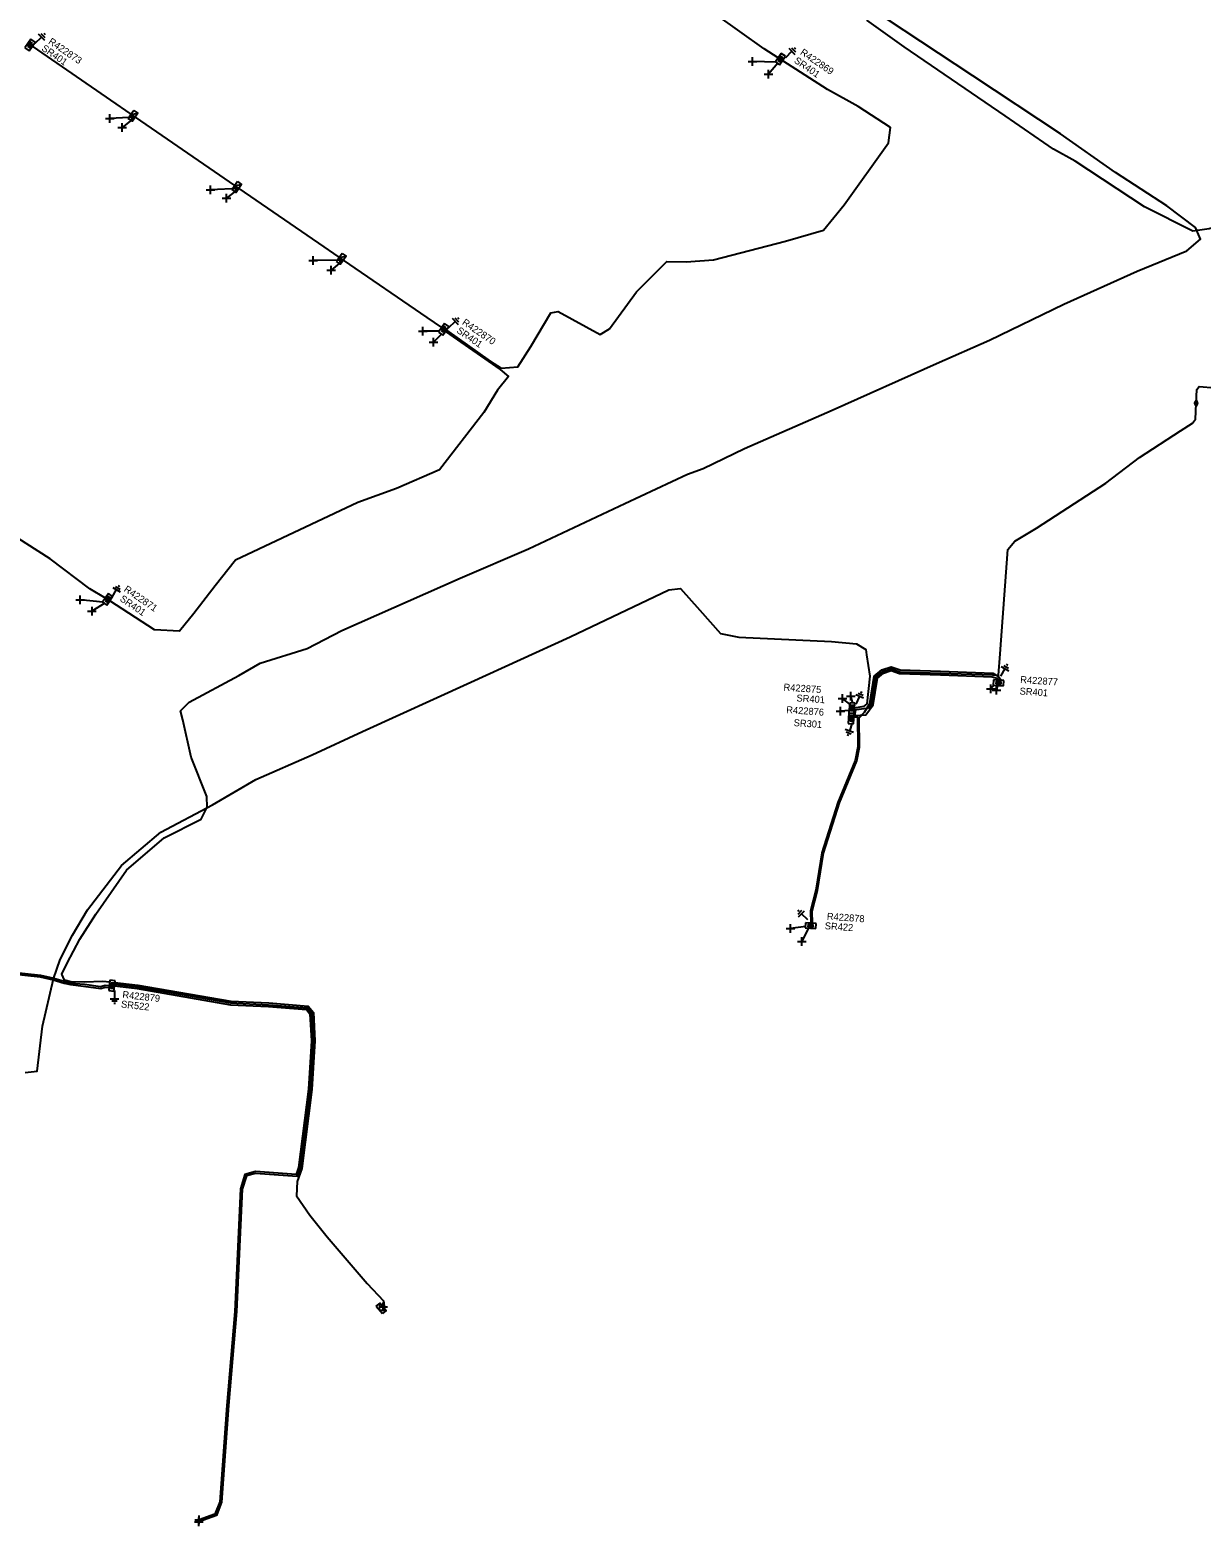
# Model space of a CAD drawing. Extents: x -540466 to -537383, y -1184038 to -1179972.
# Drawn here: x -538742.6 to -538574.2, y -1181559 to -1181344 of the extents above; entities that cross this region are included whole.
import ezdxf

# ---------------------------------------------------------------- set-up
doc = ezdxf.new("R2010")
doc.units = 0
for name, color, linetype in [('Vrstva 1', 7, 'Continuous'), ('Vrstva 14', 7, 'Continuous'), ('Vrstva 15', 7, 'Continuous'), ('Vrstva 19', 7, 'Continuous'), ('Vrstva 28', 7, 'Continuous'), ('Vrstva 29', 7, 'Continuous'), ('Vrstva 30', 7, 'Continuous'), ('Vrstva 31', 7, 'Continuous'), ('Vrstva 34', 7, 'Continuous'), ('Vrstva 4', 7, 'Continuous'), ('Vrstva 5', 7, 'Continuous'), ('Vrstva 52', 7, 'Continuous'), ('Vrstva 59', 7, 'Continuous'), ('Vrstva 8', 7, 'Continuous'), ('Vrstva 9', 7, 'Continuous')]:
    doc.layers.add(name, color=color, linetype=linetype)

# ---------------------------------------------------------------- blocks, each defined once
blk = doc.blocks.new('NN870')
at = {"layer": 'Vrstva 4'}
for points in [[(0, -0.25), (0.5, 0), (0, 0.25), (-0.5, 0), (0, -0.25)], [(0.37, 0), (0, 0.19), (-0.36, 0), (0, -0.19), (0.37, 0)], [(0.24, 0), (0, 0.12), (-0.25, 0), (0, -0.12), (0.24, 0)], [(0.12, 0), (0, 0.06), (-0.13, 0), (0, -0.06), (0.12, 0)]]:
    blk.add_lwpolyline(points, dxfattribs=at)
blk = doc.blocks.new('NN800')
at = {"layer": 'Vrstva 1'}
for points in [[(-0.44, 0.44), (0.44, -0.44)], [(-0.44, -0.44), (0.44, 0.44)]]:
    blk.add_lwpolyline(points, dxfattribs=at)
blk = doc.blocks.new('NN620')
at = {"layer": 'Vrstva 8'}
for points in [[(0.75, 0), (-0.75, 0)], [(-0.75, 0), (-0.75, -0.75)], [(0.75, -0.75), (0.75, 0)], [(-0.75, -0.75), (0.75, -0.75)], [(0.37, -0.18), (-0.38, -0.18)], [(-0.38, -0.18), (-0.38, -0.56)], [(-0.38, -0.56), (0.37, -0.56)], [(0.32, -0.23), (-0.33, -0.23)], [(-0.33, -0.23), (-0.33, -0.51)], [(-0.33, -0.51), (0.32, -0.51)], [(0.27, -0.27), (-0.28, -0.27)], [(-0.28, -0.27), (-0.28, -0.46)], [(-0.28, -0.46), (0.27, -0.46)], [(0.23, -0.32), (-0.23, -0.32)], [(-0.23, -0.32), (-0.23, -0.42)], [(-0.23, -0.42), (0.23, -0.42)], [(-0.19, -0.37), (0.19, -0.37)], [(0.23, -0.42), (0.23, -0.32)], [(0.27, -0.46), (0.27, -0.27)], [(0.32, -0.51), (0.32, -0.23)], [(0.37, -0.56), (0.37, -0.18)]]:
    blk.add_lwpolyline(points, dxfattribs=at)
blk = doc.blocks.new('NN630')
at = {"layer": 'Vrstva 9'}
for points in [[(0, -0.7), (-0.7, 0)], [(-0.7, -0.7), (-0.7, 0), (0.7, 0), (0.7, -0.7)], [(-0.7, -0.7), (0.7, -0.7)], [(0, -0.7), (0.7, 0)]]:
    blk.add_lwpolyline(points, dxfattribs=at)
blk = doc.blocks.new('NN810')
at = {"layer": 'Vrstva 14'}
for points in [[(0.63, -1.89), (-0.62, -1.89)], [(0, -0.64), (0, -1.89)], [(0.39, -2.2), (-0.4, -2.2)], [(0, -2.52), (-0.12, -2.52)], [(0.14, -2.52), (0, -2.52)]]:
    blk.add_lwpolyline(points, dxfattribs=at)

msp = doc.modelspace()

# ---------------------------------------------------------------- linework, layer by layer
at = {"layer": 'Vrstva 5'}
for points in [[(-538635.05, -1181348), (-538637.06, -1181346.73), (-538647.55, -1181339.21), (-538649.24, -1181338.43), (-538651.93, -1181336.71), (-538657.92, -1181332.02), (-538662.62, -1181329.09), (-538664.2, -1181328.31), (-538666.95, -1181326.44), (-538672.44, -1181322.58), (-538679.11, -1181317.83), (-538681.73, -1181316.02), (-538688.37, -1181311.46), (-538693.84, -1181307.67), (-538696.54, -1181305.74), (-538698.24, -1181304.66), (-538708.82, -1181297.6)], [(-538731.1, -1181480.85), (-538732.14, -1181480.76), (-538734.77, -1181480.86), (-538736.7, -1181480.81), (-538737.65, -1181480.55), (-538738.02, -1181479.68), (-538737.25, -1181478.11), (-538735.41, -1181474.65), (-538733.12, -1181471.08), (-538728.73, -1181464.75), (-538723.3, -1181460.09), (-538717.99, -1181457.42), (-538717.1, -1181455.7), (-538717.16, -1181454.17), (-538719.42, -1181448.49), (-538720.64, -1181443.15), (-538720.94, -1181441.85), (-538719.73, -1181440.59), (-538712.58, -1181436.79), (-538709.51, -1181435.01), (-538702.75, -1181432.92), (-538697.77, -1181430.33), (-538680.74, -1181422.77), (-538670.9, -1181418.57), (-538657.06, -1181412.07), (-538648.04, -1181407.85), (-538645.82, -1181407.01), (-538639.87, -1181404.18), (-538627.28, -1181398.66), (-538612.28, -1181391.93), (-538604.62, -1181388.57), (-538593.96, -1181383.4), (-538583.41, -1181378.68), (-538576.25, -1181375.76), (-538574.33, -1181374.07), (-538575.03, -1181372.41), (-538579.17, -1181369.3), (-538586.54, -1181364.5), (-538594.44, -1181358.92), (-538607.04, -1181350.62), (-538619.44, -1181342.39)], [(-538539.08, -1181394.03), (-538539.9, -1181391.85), (-538541.08, -1181387.44), (-538543.56, -1181383.99), (-538545.38, -1181379.98), (-538547.63, -1181377.02), (-538549.74, -1181371.22), (-538550.68, -1181367.96), (-538551.82, -1181367.06), (-538553.48, -1181367.17), (-538567.11, -1181370.87), (-538573.04, -1181372.59), (-538575.39, -1181372.93), (-538582.35, -1181369.44), (-538592.34, -1181362.89), (-538595.44, -1181361.14), (-538602.38, -1181356.34), (-538616.89, -1181346.44), (-538622.28, -1181342.61)], [(-538742.3, -1181346.36), (-538730.23, -1181354.65), (-538727.48, -1181356.54), (-538715.34, -1181364.88), (-538712.57, -1181366.78), (-538700.34, -1181375.18), (-538697.55, -1181377.1), (-538685.55, -1181385.34), (-538683.45, -1181386.79)], [(-538682.71, -1181387.14), (-538676.42, -1181391.61), (-538674.84, -1181392.6), (-538672.47, -1181392.41), (-538670.6, -1181389.51), (-538667.73, -1181384.64), (-538666.68, -1181384.47), (-538660.62, -1181387.79), (-538659.29, -1181386.94), (-538655.38, -1181381.65), (-538651.02, -1181377.28), (-538648.24, -1181377.34), (-538644.31, -1181377.05), (-538633.96, -1181374.37), (-538628.5, -1181372.79), (-538625.56, -1181369.15), (-538619.17, -1181360.22), (-538618.88, -1181358.01), (-538623.53, -1181355.02), (-538627.92, -1181352.55), (-538634.37, -1181348.43)], [(-538682.86, -1181387.34), (-538674.98, -1181392.8), (-538673.81, -1181393.81), (-538675.36, -1181395.77), (-538677.36, -1181398.98), (-538683.73, -1181407.21), (-538689.88, -1181409.92), (-538695.46, -1181411.93), (-538713.06, -1181420.22), (-538715.99, -1181423.89), (-538719.06, -1181427.87), (-538721.09, -1181430.43), (-538724.7, -1181430.21), (-538731.13, -1181426.05)], [(-538731.75, -1181425.68), (-538733.99, -1181424.3), (-538739.67, -1181420), (-538746.06, -1181415.93), (-538748.8, -1181414.05), (-538754.84, -1181409.68), (-538761.04, -1181405.53), (-538763.85, -1181403.72), (-538775.96, -1181395.29)], [(-538574.92, -1181397.67), (-538574.85, -1181395.66), (-538574.48, -1181395.25), (-538572.24, -1181395.42)], [(-538624.07, -1181441.71), (-538622.03, -1181441.43), (-538621.63, -1181440.89), (-538620.99, -1181437.01), (-538620, -1181436.2), (-538618.77, -1181435.81), (-538617.55, -1181436.23), (-538611.69, -1181436.42), (-538604.22, -1181436.7), (-538603.34, -1181436.74), (-538603.11, -1181433.67), (-538601.99, -1181418.67), (-538601.01, -1181417.48), (-538597.88, -1181415.62), (-538587.94, -1181409.16), (-538583.06, -1181405.46), (-538577.19, -1181401.62), (-538575.45, -1181400.54), (-538575.05, -1181399.96), (-538574.92, -1181397.67)], [(-538743.27, -1181493.84), (-538741.58, -1181493.63), (-538740.8, -1181487.17), (-538739.22, -1181480.38), (-538738.23, -1181477.57), (-538736.5, -1181474.08), (-538734.34, -1181470.43), (-538729.42, -1181464.06), (-538723.78, -1181459.31), (-538716.34, -1181455.38), (-538710.12, -1181451.72), (-538702.03, -1181448.2), (-538694.81, -1181444.83), (-538679.22, -1181437.75), (-538664.93, -1181431.23), (-538650.73, -1181424.47), (-538649.07, -1181424.28), (-538646.31, -1181427.39), (-538643.31, -1181430.75), (-538640.68, -1181431.27), (-538627.38, -1181431.9), (-538623.77, -1181432.25), (-538622.44, -1181433.06), (-538622.33, -1181433.81), (-538621.86, -1181436.86), (-538622.28, -1181440.83), (-538622.75, -1181441.25), (-538624.05, -1181441.49)], [(-538630.08, -1181472.37), (-538630.12, -1181470.62), (-538629.37, -1181467.69), (-538628.52, -1181462.31), (-538626.23, -1181455.09), (-538623.73, -1181449.05), (-538623.33, -1181447.07), (-538623.38, -1181442.85), (-538622.62, -1181442.07), (-538621.87, -1181440.79), (-538621.22, -1181436.88), (-538620.12, -1181435.98), (-538618.77, -1181435.55), (-538617.5, -1181435.98), (-538611.68, -1181436.17), (-538604.18, -1181436.45), (-538603.36, -1181436.92), (-538602.99, -1181437.47)], [(-538624.12, -1181442.54), (-538622.42, -1181442.42), (-538621.39, -1181440.99), (-538620.76, -1181437.14), (-538619.88, -1181436.42), (-538618.77, -1181436.07), (-538617.6, -1181436.48), (-538611.7, -1181436.67), (-538604.26, -1181436.95), (-538603.52, -1181437.14), (-538603.31, -1181437.45)], [(-538624.14, -1181442.74), (-538623.64, -1181442.71), (-538623.58, -1181447.05), (-538623.97, -1181448.97), (-538626.47, -1181455.01), (-538628.76, -1181462.25), (-538629.61, -1181467.64), (-538630.38, -1181470.6), (-538630.33, -1181472.35)], [(-538624.11, -1181442.38), (-538623.96, -1181442.36), (-538623.93, -1181441.9), (-538624.07, -1181441.9)], [(-538808.6, -1181453.19), (-538807.69, -1181453.79), (-538807.62, -1181453.71), (-538806.51, -1181453.14), (-538797.82, -1181454.53), (-538789.86, -1181460.41), (-538782.23, -1181464.71), (-538778.25, -1181467.41), (-538773.07, -1181470.61), (-538767.48, -1181473.44), (-538763.85, -1181474.33), (-538758.84, -1181475.03), (-538758.7, -1181477.46), (-538753.19, -1181478.69), (-538750.86, -1181479.3), (-538745.96, -1181479.57), (-538741.11, -1181480.09), (-538739.24, -1181480.49), (-538737.7, -1181480.97), (-538736.76, -1181481.19), (-538734.89, -1181481.41), (-538732.4, -1181481.76), (-538731.77, -1181481.57), (-538731.19, -1181481.59)], [(-538808.44, -1181452.94), (-538807.64, -1181453.47), (-538807.34, -1181453.25), (-538806.55, -1181452.88), (-538797.71, -1181454.3), (-538789.73, -1181460.2), (-538782.1, -1181464.5), (-538778.12, -1181467.2), (-538772.94, -1181470.4), (-538767.38, -1181473.17), (-538763.81, -1181474.1), (-538758.6, -1181474.81), (-538758.46, -1181477.26), (-538753.13, -1181478.45), (-538750.82, -1181479.06), (-538745.94, -1181479.32), (-538741.09, -1181479.85), (-538739.18, -1181480.25), (-538737.67, -1181480.71), (-538736.73, -1181480.97), (-538734.75, -1181481.15), (-538732.45, -1181481.49), (-538731.78, -1181481.29), (-538731.16, -1181481.33)]]:
    msp.add_lwpolyline(points, dxfattribs=at)
at = {"layer": 'Vrstva 52'}
for points in [[(-538730.43, -1181481.39), (-538727.16, -1181481.77), (-538713.78, -1181484.09), (-538708.31, -1181484.34), (-538702.86, -1181484.78), (-538702.34, -1181485.41), (-538702.12, -1181489.28), (-538702.57, -1181496.23), (-538703.99, -1181507.5), (-538704.33, -1181508.49), (-538710.17, -1181508.07), (-538711.68, -1181508.49), (-538712.34, -1181510.56), (-538713.14, -1181528.16), (-538714.3, -1181541.66), (-538715.32, -1181555.51), (-538716, -1181557.29), (-538718.29, -1181558.11)], [(-538730.4, -1181481.14), (-538727.12, -1181481.52), (-538713.75, -1181483.84), (-538708.29, -1181484.09), (-538702.74, -1181484.54), (-538702.1, -1181485.31), (-538701.87, -1181489.28), (-538702.32, -1181496.25), (-538703.75, -1181507.56), (-538704.17, -1181508.76), (-538710.15, -1181508.33), (-538711.48, -1181508.69), (-538712.1, -1181510.6), (-538712.89, -1181528.18), (-538714.05, -1181541.68), (-538715.08, -1181555.57), (-538715.8, -1181557.49), (-538718.31, -1181558.38)], [(-538730.37, -1181480.9), (-538727.08, -1181481.27), (-538713.72, -1181483.59), (-538708.27, -1181483.84), (-538702.61, -1181484.3), (-538701.85, -1181485.21), (-538701.62, -1181489.28), (-538702.07, -1181496.27), (-538703.51, -1181507.62), (-538704.17, -1181509.48), (-538704.26, -1181511.56), (-538702.34, -1181514.34), (-538699.86, -1181517.43), (-538694.14, -1181524.17), (-538691.79, -1181526.66), (-538691.69, -1181527.37), (-538691.82, -1181527.49)]]:
    msp.add_lwpolyline(points, dxfattribs=at)
at = {"layer": 'Vrstva 59'}
for points in [[(-538635.25, -1181348.63), (-538638.7, -1181348.53)], [(-538635.09, -1181348.79), (-538636.43, -1181350.35)], [(-538727.48, -1181356.54), (-538731.1, -1181356.73)], [(-538727.48, -1181356.54), (-538729.33, -1181358.03)], [(-538712.57, -1181366.78), (-538716.64, -1181367)], [(-538712.57, -1181366.78), (-538714.36, -1181368.2)], [(-538697.55, -1181377.1), (-538701.89, -1181377.14)], [(-538697.55, -1181377.1), (-538699.31, -1181378.51)], [(-538683.73, -1181387.32), (-538686.11, -1181387.32)], [(-538683.37, -1181387.67), (-538684.59, -1181388.88)], [(-538732.11, -1181426.26), (-538735.39, -1181425.91)], [(-538731.84, -1181426.4), (-538733.72, -1181427.53)], [(-538603.99, -1181438.12), (-538604.44, -1181438.71)], [(-538603.48, -1181438.16), (-538603.62, -1181438.9)], [(-538624.74, -1181440.89), (-538625.79, -1181440.08)], [(-538624.3, -1181440.75), (-538624.57, -1181439.77)], [(-538624.8, -1181441.79), (-538626.05, -1181441.89)], [(-538631.06, -1181472.87), (-538633.25, -1181473.14)], [(-538630.65, -1181473.03), (-538631.61, -1181475)]]:
    msp.add_lwpolyline(points, dxfattribs=at)

# ---------------------------------------------------------------- block references
at = {"layer": 'Vrstva 15'}
for p, rotation in [((-538742.29, -1181346.37), 135), ((-538634.39, -1181348.42), 135), ((-538682.81, -1181387.23), 135), ((-538731.13, -1181426.05), 148.46816385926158), ((-538603.31, -1181437.45), 151.49657228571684), ((-538624.05, -1181441.49), 156.7964249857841), ((-538624.16, -1181442.98), -19.318794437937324), ((-538630.33, -1181472.35), -135)]:
    msp.add_blockref('NN810', p, dxfattribs=dict(at, rotation=rotation))
msp.add_blockref('NN810', (-538730.43, -1181481.39), dxfattribs=at)
at = {"layer": 'Vrstva 19', "rotation": 88.0054307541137}
msp.add_blockref('NN870', (-538574.92, -1181397.67), dxfattribs=at)
at = {"layer": 'Vrstva 28'}
for p, rotation in [((-538742.29, -1181346.37), -124.37427226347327), ((-538634.39, -1181348.42), -124.37427228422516), ((-538682.81, -1181387.23), -124.37427220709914), ((-538731.13, -1181426.05), -124.3742723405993), ((-538603.31, -1181437.45), -3.9852694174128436), ((-538624.05, -1181441.49), -93.98313891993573), ((-538624.15, -1181442.98), -93.98313891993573), ((-538630.33, -1181472.35), -3.972436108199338), ((-538730.43, -1181481.39), -96.41697496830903)]:
    msp.add_blockref('NN620', p, dxfattribs=dict(at, rotation=rotation))
at = {"layer": 'Vrstva 31'}
for p, rotation in [((-538727.48, -1181356.54), -124.47646949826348), ((-538712.57, -1181366.78), -124.47438882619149), ((-538697.55, -1181377.1), -124.4808055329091), ((-538691.82, -1181527.49), -49.908330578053)]:
    msp.add_blockref('NN630', p, dxfattribs=dict(at, rotation=rotation))
at = {"layer": 'Vrstva 34'}
for p, rotation in [((-538638.7, -1181348.53), 45), ((-538636.43, -1181350.35), 45), ((-538731.1, -1181356.73), 44.99999995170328), ((-538729.33, -1181358.03), 45), ((-538716.64, -1181367), 45), ((-538714.36, -1181368.2), 45), ((-538701.89, -1181377.14), 45), ((-538699.31, -1181378.51), 45), ((-538686.11, -1181387.32), 45), ((-538684.59, -1181388.88), 44.99999995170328), ((-538735.39, -1181425.91), 45), ((-538733.72, -1181427.53), -45), ((-538625.79, -1181440.08), 45), ((-538624.57, -1181439.77), 44.99999995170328), ((-538604.44, -1181438.71), 44.99999995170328), ((-538603.62, -1181438.9), 45.000000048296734), ((-538626.05, -1181441.89), 45), ((-538633.25, -1181473.14), 44.99999995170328), ((-538631.61, -1181475), 45), ((-538691.82, -1181527.49), 45.00000009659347), ((-538718.31, -1181558.38), 45), ((-538718.29, -1181558.11), 44.99999995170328)]:
    msp.add_blockref('NN800', p, dxfattribs=dict(at, rotation=rotation))

# ---------------------------------------------------------------- texts
at = {"layer": 'Vrstva 29'}
for s, rotation, p in [('R422873', 325.626, (-538740.04, -1181345.9)), ('R422869', 325.626, (-538631.95, -1181347.45)), ('R422870', 325.626, (-538680.56, -1181386.26)), ('R422871', 325.626, (-538729.18, -1181424.6)), ('R422877', 356.015, (-538600.25, -1181437.84)), ('R422875', 356.017, (-538634.28, -1181438.93)), ('R422876', 356.017, (-538633.89, -1181442.18)), ('R422878', 356.028, (-538628.05, -1181471.87)), ('R422879', 353.583, (-538729.35, -1181483.1))]:
    msp.add_text(s, height=1, rotation=rotation, dxfattribs=at).set_placement(p)
at = {"layer": 'Vrstva 30'}
for s, rotation, p in [('SR401', 325.626, (-538741.02, -1181346.87)), ('SR401', 325.626, (-538632.83, -1181348.63)), ('SR401', 325.626, (-538681.34, -1181387.43)), ('SR401', 325.626, (-538729.76, -1181425.97)), ('SR401', 356.017, (-538632.42, -1181440.49)), ('SR401', 356.015, (-538600.34, -1181439.5)), ('SR301', 356.017, (-538632.82, -1181444.04)), ('SR422', 356.028, (-538628.35, -1181473.23)), ('SR522', 353.583, (-538729.54, -1181484.47))]:
    msp.add_text(s, height=1, rotation=rotation, dxfattribs=at).set_placement(p)

doc.saveas('drawing.dxf')
